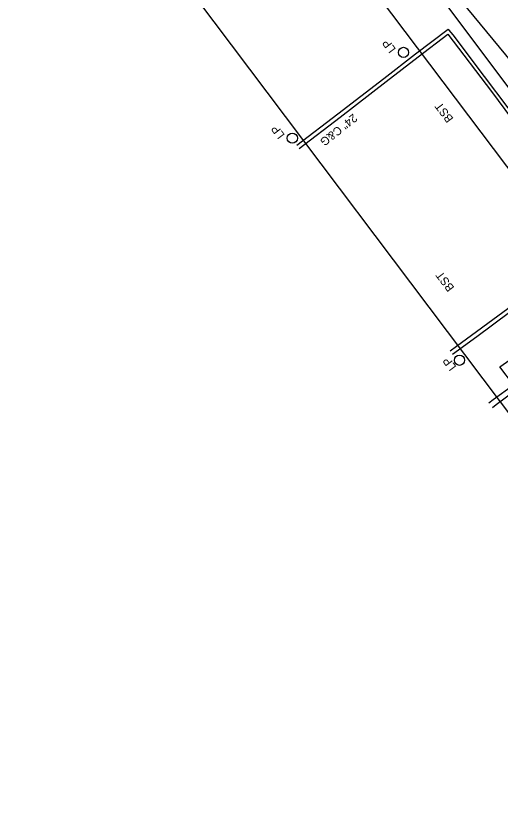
# Model space of a CAD drawing. Extents: x 1262092 to 1264624, y 774970 to 778314.
# Drawn here: x 1263925.8 to 1264159.5, y 775002.7 to 775381.8 of the extents above; entities that cross this region are included whole.
import ezdxf

# ---------------------------------------------------------------- set-up
doc = ezdxf.new("R2010")
doc.units = 0
for name, color, linetype in [('COGO Default Parcel', 7, 'Continuous'), ('Exist Right of Way Line', 7, 'Continuous'), ('Exist Roads Curbs', 7, 'Continuous'), ('Exist Roads EOP Other', 7, 'Continuous'), ('Exist Utilities Gas UG Line SUE LOS B', 7, 'Continuous'), ('Exist Utilities Other Pole Text', 7, 'Continuous'), ('Exist Utilities Power UG Cable SUE LOS B', 7, 'Continuous'), ('Exist Utilities Telephone UG FO SUE LOS B', 7, 'Continuous'), ('Prop Horizontal Alignment', 7, 'Continuous'), ('Prop Superelevation Label', 7, 'Continuous'), ('Sheet Sticker Incomplete CELL', 7, 'Continuous')]:
    doc.layers.add(name, color=color, linetype=linetype)

msp = doc.modelspace()

# ---------------------------------------------------------------- linework, layer by layer
at = {"layer": 'COGO Default Parcel'}
msp.add_line((1264304.64, 775002.74), (1263276.19, 776368.79), dxfattribs=at)
at = {"layer": 'Exist Right of Way Line'}
msp.add_line((1263350.65, 776386.89), (1264378.08, 775022.83), dxfattribs=at)
at = {"layer": 'Exist Roads Curbs'}
for points in [[(1264061.41, 775319.29), (1264081.04, 775334.41), (1264103.25, 775351.56), (1264118.64, 775363.4), (1264134.27, 775375.34)], [(1264136.63, 775372.52), (1264151.76, 775352.42), (1264163.03, 775337.36), (1264173.02, 775324.26), (1264192.8, 775297.95), (1264211.31, 775273.49), (1264200.24, 775265.33), (1264188.61, 775256.9), (1264174.1, 775246.08), (1264163.92, 775238.67), (1264148.1, 775226.88), (1264136.5, 775218.37)]]:
    msp.add_lwpolyline(points, dxfattribs=at)
at = {"layer": 'Exist Roads EOP Other'}
for points in [[(1264134.27, 775375.34), (1264134.71, 775374.86), (1264136.63, 775372.52)], [(1264062.55, 775317.76), (1264082.21, 775332.9), (1264104.42, 775350.05), (1264119.8, 775361.89), (1264134.23, 775372.91)], [(1264134.23, 775372.91), (1264155.21, 775345.24), (1264170.88, 775324.15), (1264182.6, 775308.5), (1264198.33, 775287.75), (1264208.42, 775274.19), (1264199.44, 775267.31), (1264191.82, 775261.66), (1264177.13, 775250.92), (1264163.12, 775240.4), (1264138.43, 775222.15), (1264135.35, 775219.92)]]:
    msp.add_lwpolyline(points, dxfattribs=at)
at = {"layer": 'Exist Utilities Gas UG Line SUE LOS B'}
for centre in [(1264112.77, 775364.1), (1264059.17, 775322.68), (1264139.82, 775215.55)]:
    msp.add_circle(centre, 2.46, dxfattribs=at)
at = {"layer": 'Exist Utilities Power UG Cable SUE LOS B'}
msp.add_lwpolyline([(1264395.36, 775040.74), (1264370.8, 775076.36), (1264340.19, 775112.15), (1264308.39, 775149.99), (1264277.8, 775188.45), (1264254.82, 775218.46), (1264230.51, 775255.61), (1264208, 775290.17), (1264185.34, 775318.09), (1264158.04, 775354.59), (1264133.61, 775386.92), (1264107.25, 775423.32), (1264089.56, 775447.66), (1264061.08, 775477.65), (1264037.85, 775505.73), (1264032.45, 775511.96), (1264026.57, 775514.09), (1263970.61, 775511.19)], dxfattribs=at)
at = {"layer": 'Exist Utilities Telephone UG FO SUE LOS B'}
msp.add_lwpolyline([(1264412.43, 775054.27), (1264383.09, 775084.33), (1264350.27, 775127.37), (1264319.47, 775167.42), (1264288.52, 775206.2), (1264253.33, 775248.38), (1264233.02, 775276.08), (1264197.49, 775318.53), (1264165.2, 775359.15), (1264131.6, 775400.04), (1264102.3, 775438.18), (1264079.45, 775463.73), (1264046.01, 775506.17), (1264034.16, 775523.07), (1264026.26, 775546.1), (1264015.26, 775566.11), (1263989.3, 775607.52), (1263955.25, 775658.94), (1263921.26, 775710.27), (1263888.91, 775754.45), (1263860.31, 775793.96), (1263832.43, 775832.72), (1263818.26, 775866.25), (1263816.28, 775877)], dxfattribs=at)
at = {"layer": 'Prop Superelevation Label'}
msp.add_lwpolyline([(1264153.9, 775195), (1264156.1, 775196.66), (1264165.77, 775203.68), (1264159.27, 775212.41), (1264164.02, 775215.69), (1264178.73, 775196.36), (1264173.98, 775192.79), (1264167.44, 775201.42), (1264157.56, 775193.98), (1264155.72, 775192.55)], dxfattribs=at)

# ---------------------------------------------------------------- texts
at = {"layer": 'Exist Utilities Other Pole Text'}
for p in [(1264109.31, 775365.69), (1264055.72, 775324.26), (1264138.48, 775212.34)]:
    msp.add_text('LP', height=4, rotation=126.9746, dxfattribs=at).set_placement(p)
at = {"layer": 'Prop Horizontal Alignment'}
for p in [(1264137.06, 775332.11), (1264137.06, 775332.11), (1264137.5, 775250.56), (1264137.5, 775250.56)]:
    msp.add_text('BST', height=4, rotation=126.9874, dxfattribs=at).set_placement(p)
at = {"layer": 'Sheet Sticker Incomplete CELL'}
msp.add_text('24" C&G', height=4, rotation=218.489, dxfattribs=at).set_placement((1264088.51, 775334.72))

doc.saveas('drawing.dxf')
